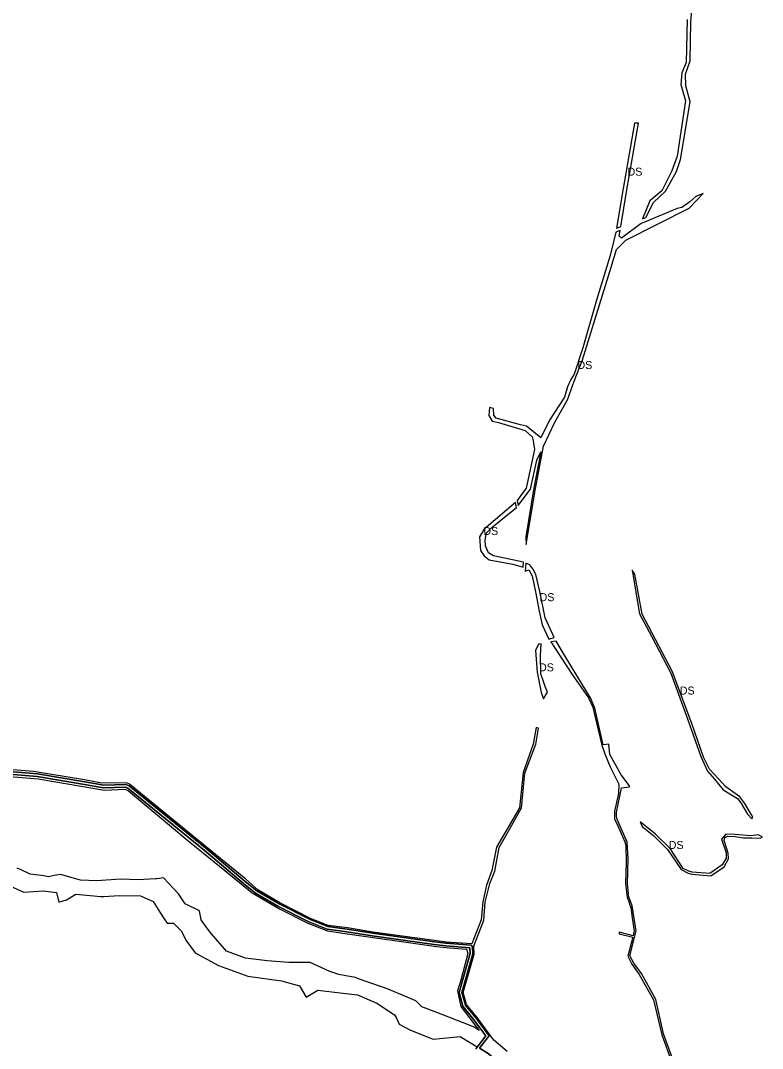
# Model space of a CAD drawing. Extents: x -477304 to -465641, y -1159113 to -1149285.
# Drawn here: x -475972 to -475138, y -1151597 to -1150441 of the extents above; entities that cross this region are included whole.
import ezdxf

# ---------------------------------------------------------------- set-up
doc = ezdxf.new("R2010")
doc.units = 0
doc.layers.add('14', color=7, linetype='Continuous')
doc.layers.add('35', color=7, linetype='Continuous')

msp = doc.modelspace()

# ---------------------------------------------------------------- linework, layer by layer
at = {"layer": '14'}
for p, q in [((-475449.4, -1151582.8), (-475460.9, -1151597.8)), ((-475456.5, -1151596.9), (-475445.7, -1151582.8))]:
    msp.add_line(p, q, dxfattribs=at)
for points in [[(-475985.3, -1151288.7), (-475953.7, -1151291.5), (-475900.6, -1151300.2), (-475879.1, -1151304.2), (-475854.5, -1151303.5), (-475851.9, -1151304.4), (-475766.1, -1151374.2), (-475721.7, -1151411.6), (-475708.4, -1151422.5), (-475683.2, -1151437.2), (-475648.2, -1151454.8), (-475627.6, -1151463.1), (-475605.6, -1151465.8), (-475577, -1151470.6), (-475507.6, -1151480.2), (-475494.5, -1151481.8), (-475467.4, -1151483.8), (-475467.3, -1151484), (-475467, -1151490.5), (-475479.4, -1151534.3), (-475475.2, -1151549.7), (-475462.7, -1151565), (-475449.4, -1151582.8)], [(-475445.7, -1151582.8), (-475460.3, -1151563.2), (-475472.4, -1151548.3), (-475476.3, -1151534.3), (-475463.9, -1151490.8), (-475464.3, -1151482.7), (-475466, -1151480.9), (-475494.2, -1151478.9), (-475507.2, -1151477.2), (-475576.5, -1151467.6), (-475605.2, -1151462.8), (-475626.9, -1151460.1), (-475647, -1151452.1), (-475681.7, -1151434.5), (-475706.7, -1151420), (-475719.8, -1151409.3), (-475764.2, -1151371.9), (-475850.4, -1151301.7), (-475854, -1151300.5), (-475878.9, -1151301.2), (-475900.1, -1151297.2), (-475953.3, -1151288.5), (-475985.1, -1151285.7)], [(-475404, -1151636.5), (-475415.6, -1151628.1), (-475440.8, -1151607.8), (-475448, -1151602.1), (-475456.5, -1151596.9)]]:
    msp.add_lwpolyline(points, dxfattribs=at)
at = {"layer": '35'}
for p, q in [((-475219, -1150442.5), (-475217.5, -1150425.1)), ((-475223.1, -1150440.3), (-475224.1, -1150488.4)), ((-475219.8, -1150486.8), (-475219, -1150442.5)), ((-475224.1, -1150488.4), (-475229, -1150500)), ((-475224.8, -1150501.7), (-475219.8, -1150486.8)), ((-475229, -1150500), (-475230.3, -1150513.3)), ((-475282.2, -1150556.9), (-475294.9, -1150630.3)), ((-475290.7, -1150631.8), (-475277.7, -1150556.9)), ((-475277.7, -1150556.9), (-475282.2, -1150556.9)), ((-475234.4, -1150593.8), (-475240.1, -1150610.2)), ((-475294.9, -1150630.3), (-475302.5, -1150674.8)), ((-475297.7, -1150673.1), (-475290.7, -1150631.8)), ((-475205.2, -1150635.8), (-475213.1, -1150639.1)), ((-475269.4, -1150663), (-475260.9, -1150646.1)), ((-475273.3, -1150664.4), (-475269.4, -1150663)), ((-475298.5, -1150677.6), (-475303.4, -1150679.4)), ((-475302.5, -1150674.8), (-475297.7, -1150673.1)), ((-475299.6, -1150683.9), (-475298.5, -1150677.6)), ((-475270.8, -1150668.2), (-475274.8, -1150669.7)), ((-475303.4, -1150679.4), (-475309.4, -1150705.5)), ((-475302.3, -1150698.7), (-475292, -1150688.4)), ((-475311.5, -1150728.6), (-475302.3, -1150698.7)), ((-475349.9, -1150838.9), (-475353.8, -1150845.1)), ((-475357.5, -1150868), (-475350.1, -1150846.7)), ((-475371.7, -1150893), (-475357.5, -1150868)), ((-475445.1, -1150876.3), (-475445.9, -1150885.5)), ((-475445.9, -1150885.5), (-475442.1, -1150891.9)), ((-475440.7, -1150877.5), (-475445.1, -1150876.3)), ((-475442.1, -1150891.9), (-475435, -1150893.4)), ((-475410.5, -1150896), (-475437.7, -1150888.6)), ((-475377.9, -1150890.7), (-475387.7, -1150910.4)), ((-475384.7, -1150919.9), (-475371.7, -1150893)), ((-475393.6, -1150967.5), (-475384.7, -1150919.9)), ((-475387.7, -1150926.2), (-475395.5, -1150966.9)), ((-475395.5, -1150966.9), (-475404.5, -1151021.9)), ((-475403.9, -1151030.5), (-475393.6, -1150967.5)), ((-475442.1, -1151010.9), (-475415, -1150988.8)), ((-475414.2, -1150981.1), (-475413.1, -1150986.5)), ((-475448.8, -1151017.4), (-475442.1, -1151010.9)), ((-475456.4, -1151021.9), (-475455.5, -1151037.1)), ((-475404.5, -1151021.9), (-475403.9, -1151030.5)), ((-475445.8, -1151047.7), (-475419, -1151052.6)), ((-475419, -1151052.6), (-475407.4, -1151056.1)), ((-475407.4, -1151056.1), (-475407, -1151050.4)), ((-475404.4, -1151051.4), (-475405.2, -1151060.5)), ((-475405.2, -1151060.5), (-475400.9, -1151058.9)), ((-475388.5, -1151083.3), (-475393, -1151064.4)), ((-475273.5, -1151108.9), (-475281.7, -1151064)), ((-475378.4, -1151137.1), (-475372.7, -1151135.1)), ((-475370.3, -1151139.1), (-475376.2, -1151140.1)), ((-475376.2, -1151140.1), (-475352.3, -1151176.5)), ((-475372.7, -1151135.1), (-475374.2, -1151131.5)), ((-475390, -1151142.6), (-475393.4, -1151149.5)), ((-475393.4, -1151149.5), (-475391.6, -1151174)), ((-475387.1, -1151142.2), (-475390, -1151142.6)), ((-475387.9, -1151155.3), (-475387.1, -1151142.2)), ((-475241.5, -1151175), (-475222.6, -1151226.4)), ((-475352.3, -1151176.5), (-475333.8, -1151203)), ((-475384.7, -1151204.1), (-475380.1, -1151196.6)), ((-475380.1, -1151196.6), (-475382.5, -1151190.1)), ((-475327.2, -1151221.6), (-475319, -1151256.1)), ((-475321.2, -1151239.1), (-475326.9, -1151214.4)), ((-475390.1, -1151236.9), (-475392.9, -1151236.4)), ((-475317.3, -1151255.9), (-475321.2, -1151239.1)), ((-475311.1, -1151254.9), (-475317.3, -1151255.9)), ((-475309.9, -1151266.6), (-475311.1, -1151254.9)), ((-475297.2, -1151289.3), (-475309.9, -1151266.6)), ((-475958.1, -1151285.8), (-475985.8, -1151283.6)), ((-475288, -1151301.7), (-475297.2, -1151289.3)), ((-475200.1, -1151285.4), (-475192.4, -1151294.5)), ((-475935.1, -1151296.9), (-475878.2, -1151306.6)), ((-475850.1, -1151299.8), (-475853.5, -1151298.6)), ((-475763.3, -1151370.8), (-475850.1, -1151299.8)), ((-475287.7, -1151303.1), (-475288, -1151301.7)), ((-475192.4, -1151294.5), (-475182.4, -1151306.3)), ((-475878.2, -1151306.6), (-475854.9, -1151305.6)), ((-475302.5, -1151331.6), (-475298.6, -1151313.4)), ((-475298.6, -1151313.4), (-475297, -1151303.9)), ((-475297, -1151303.9), (-475287.7, -1151303.1)), ((-475182.4, -1151306.3), (-475166.4, -1151316)), ((-475166.4, -1151316), (-475162.6, -1151321.1)), ((-475425.5, -1151355.3), (-475409.4, -1151326.6)), ((-475302.3, -1151335.6), (-475302.5, -1151331.6)), ((-475302.1, -1151338.5), (-475302.3, -1151335.6)), ((-475150.3, -1151338.8), (-475149, -1151337)), ((-475304.7, -1151338.9), (-475301.1, -1151346.8)), ((-475301.1, -1151346.8), (-475293, -1151364.7)), ((-475260.6, -1151358), (-475245.1, -1151373.4)), ((-475177.8, -1151358.6), (-475168.9, -1151358.8)), ((-475719.1, -1151406.9), (-475763.3, -1151370.8)), ((-475293, -1151364.7), (-475292.1, -1151369)), ((-475292.1, -1151369), (-475291.7, -1151388.1)), ((-475245.1, -1151373.4), (-475229.9, -1151395.8)), ((-475291.7, -1151388.1), (-475292.4, -1151411.7)), ((-475290.2, -1151412), (-475289.5, -1151383.8)), ((-475196.4, -1151403.2), (-475181.4, -1151392.8)), ((-475946.2, -1151403.2), (-475961.6, -1151401)), ((-475941.5, -1151404), (-475946.2, -1151403.2)), ((-475934.2, -1151402.8), (-475941.5, -1151404)), ((-475927.5, -1151401.7), (-475934.2, -1151402.8)), ((-475905.2, -1151407.9), (-475927.5, -1151401.7)), ((-475444.9, -1151411.5), (-475439.4, -1151397.6)), ((-475229.9, -1151395.8), (-475222, -1151400.2)), ((-475987.8, -1151412.6), (-475968.8, -1151421.2)), ((-475840.4, -1151407.6), (-475860.3, -1151406.9)), ((-475450.1, -1151432.6), (-475444.9, -1151411.5)), ((-475932, -1151421.6), (-475929.5, -1151432.7)), ((-475920.9, -1151429.9), (-475910.2, -1151423.6)), ((-475879, -1151426.3), (-475861.5, -1151425.2)), ((-475861.5, -1151425.2), (-475837.8, -1151425.5)), ((-475837.8, -1151425.5), (-475823.4, -1151431.7)), ((-475787.3, -1151434.5), (-475795.1, -1151423.2)), ((-475929.5, -1151432.7), (-475920.9, -1151429.9)), ((-475823.4, -1151431.7), (-475815.8, -1151443.8)), ((-475771.4, -1151442.3), (-475787.3, -1151434.5)), ((-475681.2, -1151440.2), (-475649.6, -1151456.4)), ((-475646.4, -1151450.8), (-475681.1, -1151433.3)), ((-475452.9, -1151432.3), (-475454.8, -1151452.3)), ((-475451.6, -1151452.7), (-475450.1, -1151432.6)), ((-475288.7, -1151431.7), (-475287.3, -1151435.9)), ((-475287.3, -1151435.9), (-475286.3, -1151438.6)), ((-475454.8, -1151452.3), (-475465.3, -1151479.6)), ((-475463, -1151482.2), (-475451.6, -1151452.7)), ((-475807.5, -1151456.1), (-475800.4, -1151456.1)), ((-475800.4, -1151456.1), (-475791.7, -1151465.2)), ((-475649.6, -1151456.4), (-475627.4, -1151464.9)), ((-475280.3, -1151464.8), (-475281.1, -1151460.4)), ((-475791.7, -1151465.2), (-475786.6, -1151475.4)), ((-475627.4, -1151464.9), (-475612.7, -1151467)), ((-475612.7, -1151467), (-475504.9, -1151482.3)), ((-475299.4, -1151466.3), (-475299.4, -1151467.1)), ((-475299.4, -1151467.1), (-475299.4, -1151468.4)), ((-475287.5, -1151493.1), (-475283, -1151475.3)), ((-475283, -1151475.3), (-475280.3, -1151464.8)), ((-475504.9, -1151482.3), (-475490.3, -1151484.1)), ((-475283.1, -1151501.1), (-475287.5, -1151493.1)), ((-475614.8, -1151513.8), (-475624.7, -1151510.5)), ((-475285.4, -1151502.3), (-475277, -1151513.9)), ((-475606.6, -1151515.4), (-475614.8, -1151513.8)), ((-475658.9, -1151526.6), (-475651.2, -1151539.5)), ((-475651.2, -1151539.5), (-475638.2, -1151531.7)), ((-475638.2, -1151531.7), (-475613.3, -1151534.7)), ((-475528.2, -1151543.6), (-475559.2, -1151530.3)), ((-475613.3, -1151534.7), (-475593.8, -1151536.9)), ((-475527, -1151544.8), (-475528.2, -1151543.6)), ((-475521.2, -1151550.2), (-475527, -1151544.8)), ((-475504.6, -1151556.5), (-475521.2, -1151550.2)), ((-475468.7, -1151570.7), (-475504.6, -1151556.5)), ((-475534.2, -1151576.4), (-475508.5, -1151586.5)), ((-475456.6, -1151592.1), (-475449.4, -1151582.8)), ((-475446.3, -1151583.7), (-475454.1, -1151593.9)), ((-475449.4, -1151582.8), (-475451.2, -1151580.4)), ((-475445.7, -1151582.8), (-475446.3, -1151583.7)), ((-475425.3, -1151600.6), (-475440.2, -1151587.9)), ((-475251.6, -1151581.7), (-475240.7, -1151611.9)), ((-475459, -1151595.4), (-475456.6, -1151592.1)), ((-475454.1, -1151593.9), (-475456.5, -1151596.9))]:
    msp.add_line(p, q, dxfattribs=at)
for points in [[(-475219.7, -1150532.7), (-475224.5, -1150514.7), (-475224.8, -1150501.7)], [(-475230.3, -1150513.3), (-475225, -1150531.6), (-475234.4, -1150593.8)], [(-475235.1, -1150611.2), (-475230.4, -1150597.5), (-475219.7, -1150532.7)], [(-475240.1, -1150610.2), (-475251.5, -1150632.9), (-475265, -1150644.2), (-475273.3, -1150664.4)], [(-475260.9, -1150646.1), (-475247.4, -1150633.3), (-475235.1, -1150611.2)], [(-475292, -1150688.4), (-475220.9, -1150652.2), (-475205.2, -1150635.8)], [(-475213.1, -1150639.1), (-475220.2, -1150645.3), (-475229, -1150651.4)], [(-475229, -1150651.4), (-475234.3, -1150652.6), (-475270.8, -1150668.2)], [(-475274.8, -1150669.7), (-475296.7, -1150686.1), (-475299.6, -1150683.9)], [(-475309.4, -1150705.5), (-475324.9, -1150755.8), (-475340.4, -1150809.3), (-475349.9, -1150838.9)], [(-475350.1, -1150846.7), (-475340.6, -1150822.8), (-475325, -1150771.8), (-475311.5, -1150728.6)], [(-475353.8, -1150845.1), (-475357.4, -1150853.4), (-475361.1, -1150864.8), (-475377.9, -1150890.7)], [(-475437.7, -1150888.6), (-475440.3, -1150885), (-475440.7, -1150877.5)], [(-475435, -1150893.4), (-475405.1, -1150902.4), (-475397.2, -1150909.3)], [(-475387.7, -1150910.4), (-475403.8, -1150897.6), (-475410.5, -1150896)], [(-475397.2, -1150909.3), (-475396, -1150914.1), (-475394.5, -1150923.7)], [(-475394.5, -1150923.7), (-475404.2, -1150967), (-475414.2, -1150981.1)], [(-475413.1, -1150986.5), (-475399.2, -1150968.2), (-475392, -1150935.5), (-475387.7, -1150926.2)], [(-475415, -1150988.8), (-475416, -1150983.4), (-475451.4, -1151013.2), (-475456.4, -1151021.9)], [(-475449.7, -1151031.8), (-475450.3, -1151025.7), (-475448.8, -1151017.4)], [(-475407, -1151050.4), (-475440.6, -1151043.2), (-475446.2, -1151039.7), (-475449.7, -1151031.8)], [(-475455.5, -1151037.1), (-475451.1, -1151043.4), (-475445.8, -1151047.7)], [(-475393, -1151064.4), (-475396.7, -1151057.9), (-475399.8, -1151053.4), (-475404.4, -1151051.4)], [(-475400.9, -1151058.9), (-475397.4, -1151065.8), (-475393.1, -1151085.4), (-475389.3, -1151105.4), (-475386.1, -1151120.9), (-475378.4, -1151137.1)], [(-475281.7, -1151064), (-475285, -1151059.5), (-475276.6, -1151108.5)], [(-475374.2, -1151131.5), (-475382.7, -1151112.8), (-475388.5, -1151083.3)], [(-475276.6, -1151108.5), (-475263, -1151133.5), (-475241.5, -1151175)], [(-475217.8, -1151231.9), (-475239.7, -1151172.8), (-475273.5, -1151108.9)], [(-475340.7, -1151188.3), (-475359.8, -1151156.8), (-475370.3, -1151139.1)], [(-475382.5, -1151190.1), (-475385.3, -1151182.1), (-475387.4, -1151176.1), (-475387.9, -1151155.3)], [(-475391.6, -1151174), (-475387.3, -1151196.8), (-475384.7, -1151204.1)], [(-475326.9, -1151214.4), (-475331.6, -1151203), (-475340.7, -1151188.3)], [(-475333.8, -1151203), (-475329.1, -1151213.4), (-475327.2, -1151221.6)], [(-475222.6, -1151226.4), (-475207.5, -1151268.9), (-475200.1, -1151285.4)], [(-475198, -1151283.1), (-475204.5, -1151269.5), (-475217.8, -1151231.9)], [(-475392.9, -1151236.4), (-475396.1, -1151254.9), (-475407.4, -1151286.7), (-475411.7, -1151326.5)], [(-475409.4, -1151326.6), (-475405.4, -1151287.6), (-475393, -1151254.8), (-475390.1, -1151236.9)], [(-475319, -1151256.1), (-475315.4, -1151266), (-475309.7, -1151280.4)], [(-476041.1, -1151291.8), (-476022.2, -1151288.4), (-475952.7, -1151294), (-475935.1, -1151296.9)], [(-475451.2, -1151580.4), (-475462.7, -1151565), (-475475.2, -1151549.7), (-475479.4, -1151534.3), (-475467, -1151490.5), (-475467.3, -1151484), (-475467.4, -1151483.8), (-475494.5, -1151481.8), (-475507.6, -1151480.2), (-475577, -1151470.6), (-475605.6, -1151465.8), (-475627.6, -1151463.1), (-475648.2, -1151454.8), (-475683.2, -1151437.2), (-475708.4, -1151422.5), (-475721.7, -1151411.6), (-475766.1, -1151374.2), (-475851.9, -1151304.4), (-475854.5, -1151303.5), (-475879.1, -1151304.2), (-475900.6, -1151300.2), (-475953.7, -1151291.5), (-475985.3, -1151288.7)], [(-475985.1, -1151285.7), (-475953.3, -1151288.5), (-475900.1, -1151297.2), (-475878.9, -1151301.2), (-475854, -1151300.5), (-475850.4, -1151301.7), (-475764.2, -1151371.9), (-475719.8, -1151409.3), (-475706.7, -1151420), (-475681.7, -1151434.5), (-475647, -1151452.1), (-475626.9, -1151460.1), (-475605.2, -1151462.8), (-475576.5, -1151467.6), (-475507.2, -1151477.2), (-475494.2, -1151478.9), (-475466, -1151480.9), (-475464.3, -1151482.7), (-475463.9, -1151490.8), (-475476.3, -1151534.3), (-475472.4, -1151548.3), (-475460.3, -1151563.2), (-475445.7, -1151582.8)], [(-475853.5, -1151298.6), (-475881.2, -1151298.8), (-475900.5, -1151295.1), (-475958.1, -1151285.8)], [(-475309.7, -1151280.4), (-475300, -1151300.1), (-475300.3, -1151310.3)], [(-475163.9, -1151314.3), (-475179.6, -1151302.8), (-475188.3, -1151293.4), (-475198, -1151283.1)], [(-475854.9, -1151305.6), (-475851, -1151307.5), (-475786.5, -1151361.3)], [(-475300.3, -1151310.3), (-475304.7, -1151330.4), (-475304.7, -1151338.9)], [(-475149, -1151337), (-475150.6, -1151334.3), (-475158, -1151321.8), (-475163.9, -1151314.3)], [(-475162.6, -1151321.1), (-475155.3, -1151333.6), (-475150.3, -1151338.8)], [(-475411.7, -1151326.5), (-475437.5, -1151370.7), (-475442.6, -1151397.2)], [(-475289.5, -1151383.8), (-475290.5, -1151365.1), (-475302.1, -1151338.5)], [(-475197.6, -1151400.4), (-475217.4, -1151398.8), (-475221.2, -1151397.8), (-475227.4, -1151394.7), (-475242.1, -1151372.4), (-475258.8, -1151356.3), (-475275.7, -1151342.4), (-475273.7, -1151347.5), (-475260.6, -1151358)], [(-475439.4, -1151397.6), (-475434.4, -1151371), (-475425.5, -1151355.3)], [(-475173.8, -1151356.2), (-475180, -1151356.6), (-475184.5, -1151361.7), (-475179.2, -1151377.1), (-475179, -1151383.1)], [(-475176.8, -1151377.4), (-475181.6, -1151363.2), (-475180.6, -1151360.1), (-475177.8, -1151358.6)], [(-475143, -1151357.1), (-475151.5, -1151357.9), (-475165, -1151357.1), (-475173.8, -1151356.2)], [(-475168.9, -1151358.8), (-475159.7, -1151360.2), (-475150.2, -1151360.4), (-475141, -1151360.6)], [(-475141, -1151360.6), (-475138.4, -1151359), (-475143, -1151357.1)], [(-475786.5, -1151361.3), (-475742.9, -1151397), (-475712, -1151422.3), (-475681.2, -1151440.2)], [(-475179, -1151383.1), (-475183.5, -1151390.8), (-475197.6, -1151400.4)], [(-475181.4, -1151392.8), (-475176.5, -1151383.8), (-475176.8, -1151377.4)], [(-475961.6, -1151401), (-475971.8, -1151396.3), (-475976.2, -1151394.3)], [(-475819.2, -1151406.2), (-475820.9, -1151406.4), (-475840.4, -1151407.6)], [(-475795.1, -1151423.2), (-475811.9, -1151405.4), (-475819.2, -1151406.2)], [(-475442.6, -1151397.2), (-475448.8, -1151413.6), (-475452.9, -1151432.3)], [(-475222, -1151400.2), (-475217.7, -1151401.3), (-475196.4, -1151403.2)], [(-475860.3, -1151406.9), (-475886.7, -1151408.5), (-475905.2, -1151407.9)], [(-475681.1, -1151433.3), (-475705.8, -1151418.9), (-475719.1, -1151406.9)], [(-475292.4, -1151411.7), (-475290.6, -1151427.3), (-475288.7, -1151431.7)], [(-475286.8, -1151431.4), (-475288.5, -1151427), (-475290.2, -1151412)], [(-475968.8, -1151421.2), (-475947.2, -1151419.7), (-475932, -1151421.6)], [(-475910.2, -1151423.6), (-475882.3, -1151426.1), (-475879, -1151426.3)], [(-475281.1, -1151460.4), (-475284.8, -1151436.6), (-475286.8, -1151431.4)], [(-475286.3, -1151438.6), (-475284.9, -1151450.3), (-475282.5, -1151465)], [(-475815.8, -1151443.8), (-475810.2, -1151452.4), (-475807.5, -1151456.1)], [(-475763, -1151461.5), (-475769.4, -1151452.5), (-475771.4, -1151442.3)], [(-475465.3, -1151479.6), (-475494.1, -1151477.5), (-475507.1, -1151475.8), (-475576.3, -1151466.3), (-475605, -1151461.4), (-475626.5, -1151458.8), (-475646.4, -1151450.8)], [(-475719.6, -1151495.6), (-475740.8, -1151487.8), (-475757.9, -1151468.1), (-475763, -1151461.5)], [(-475786.6, -1151475.4), (-475776.2, -1151489.5), (-475749.9, -1151503.8), (-475717, -1151515.9)], [(-475282.5, -1151465), (-475283.7, -1151470.3), (-475299.4, -1151466.3)], [(-475299.4, -1151468.4), (-475284.1, -1151471.9), (-475289.8, -1151493.5), (-475285.4, -1151502.3)], [(-475490.3, -1151484.1), (-475471.2, -1151485.3), (-475469.5, -1151490.2), (-475477.4, -1151520.4)], [(-475440.2, -1151587.9), (-475459.2, -1151562.3), (-475471.2, -1151547.7), (-475474.9, -1151534.3), (-475462.5, -1151491), (-475463, -1151482.2)], [(-475671, -1151500.3), (-475695.4, -1151498.7), (-475719.6, -1151495.6)], [(-475624.7, -1151510.5), (-475646.8, -1151500.3), (-475671, -1151500.3)], [(-475239.5, -1151608.4), (-475249.5, -1151580.8), (-475258.4, -1151541.9), (-475274.4, -1151512.9), (-475283.1, -1151501.1)], [(-475717, -1151515.9), (-475679.1, -1151521), (-475658.9, -1151526.6)], [(-475559.2, -1151530.3), (-475592.5, -1151518.8), (-475596.1, -1151517.5), (-475606.6, -1151515.4)], [(-475477.4, -1151520.4), (-475481.2, -1151532.4), (-475477.3, -1151549.9), (-475456.7, -1151577)], [(-475277, -1151513.9), (-475260.9, -1151542.5), (-475251.6, -1151581.7)], [(-475593.8, -1151536.9), (-475571.8, -1151546), (-475551.9, -1151559.4), (-475549.8, -1151562.9)], [(-475549.8, -1151562.9), (-475546.7, -1151569.7), (-475534.2, -1151576.4)], [(-475456.7, -1151577), (-475462.4, -1151573.1), (-475468.7, -1151570.7)], [(-475508.5, -1151586.5), (-475478.3, -1151583.7), (-475459, -1151595.4)], [(-475456.5, -1151596.9), (-475448, -1151602.1), (-475440.8, -1151607.8), (-475415.6, -1151628.1), (-475404, -1151636.5)]]:
    msp.add_lwpolyline(points, dxfattribs=at)

# ---------------------------------------------------------------- texts
for p in [(-475290.1, -1150615.8), (-475346.4, -1150833.2), (-475452.2, -1151019.8), (-475389, -1151094.2), (-475389.6, -1151173.1), (-475231.3, -1151199.2), (-475243.8, -1151372.8)]:
    msp.add_text('DS', height=9, dxfattribs=at).set_placement(p)

doc.saveas('drawing.dxf')
